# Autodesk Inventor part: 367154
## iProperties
Created: 2006-09
Part Number: 367154
Material: 8.8 vz
Description: Zylinderschraube
Vendor: Autodesk Inc.
Document SubType Name: Modeling
Standard: DIN 912
Designer: I.Baliuc
Standards Organization: DIN
Language: de-DE
Size Designation: M6 x 20
Categories: <MemberInstance Version="R10.0.0"><Categories><Category DisplayName="Schrauben" InternalName="e4da775c-781d-43d5-af7c-5136215cf5a6" Mnemonic="FSTN"><Category Di
Density: 7.85 g/cm^3
Abmessung: M6 x 20
Author: T.Messerschmitt
Comments: DIN 912 - M6 x 20
Revision Number: 367154
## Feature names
1. Körper [Revolution]
2. Loch [Extrusion]
3. Rundung1 [Fillet]
4. Fase1 [Chamfer]
